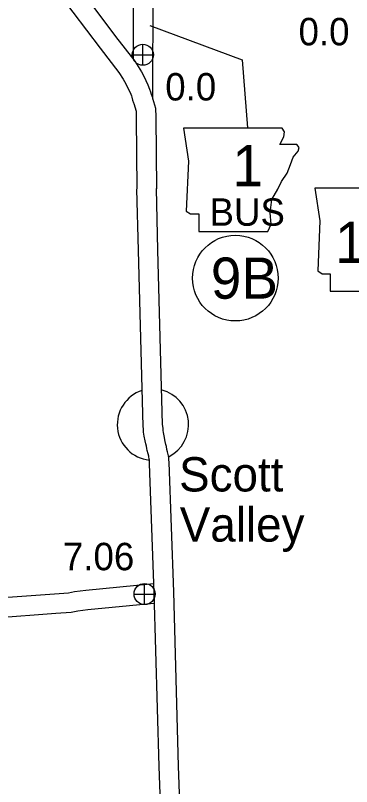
# Model space of a CAD drawing. Extents: x -939622 to -934222, y 1383701 to 1385301.
# Drawn here: x -935782 to -935766.45, y 1384146.23 to 1384181.86 of the extents above; entities that cross this region are included whole.
import ezdxf

# ---------------------------------------------------------------- set-up
doc = ezdxf.new("R2010")
doc.units = 0
for name, color, linetype in [('Level 10', 7, 'Continuous'), ('Level 21', 7, 'Continuous'), ('Level 24', 7, 'Continuous'), ('Level 25', 7, 'Continuous'), ('Level 26', 7, 'Continuous'), ('Level 27', 7, 'Continuous')]:
    doc.layers.add(name, color=color, linetype=linetype)

msp = doc.modelspace()

# ---------------------------------------------------------------- linework, layer by layer
at = {"layer": 'Level 10'}
for points in [[(-935775.638, 1384177.983), (-935775.627, 1384183.177), (-935775.684, 1384187.654), (-935778.687, 1384187.545)], [(-935776.534, 1384179.887), (-935776.527, 1384183.172), (-935776.573, 1384186.721), (-935778.655, 1384186.646)], [(-935779.255, 1384183.412), (-935777.367, 1384180.887), (-935776.471, 1384179.742), (-935776.243, 1384179.374), (-935776.172, 1384179.256), (-935776.045, 1384179.019), (-935775.96, 1384178.849), (-935775.869, 1384178.648), (-935775.787, 1384178.449), (-935775.747, 1384178.322), (-935775.719, 1384178.212), (-935775.676, 1384178.104), (-935775.657, 1384178.037), (-935775.517, 1384177.575)], [(-935779.968, 1384182.862), (-935778.082, 1384180.341), (-935777.21, 1384179.226), (-935777.011, 1384178.905), (-935776.955, 1384178.811), (-935776.845, 1384178.606), (-935776.774, 1384178.463), (-935776.695, 1384178.29), (-935776.633, 1384178.139), (-935776.613, 1384178.075), (-935776.577, 1384177.935), (-935776.528, 1384177.812), (-935776.52, 1384177.783), (-935776.414, 1384177.43)], [(-935776.414, 1384177.43), (-935776.406, 1384177.133), (-935776.376, 1384173.839)], [(-935775.517, 1384177.575), (-935775.506, 1384177.15), (-935775.476, 1384173.847)], [(-935774.547, 1384123.471), (-935774.788, 1384131.051), (-935775.054, 1384139.145), (-935775.353, 1384147.15), (-935775.575, 1384155.194), (-935775.787, 1384161.148), (-935775.795, 1384161.271), (-935775.799, 1384161.32), (-935775.803, 1384161.348), (-935775.812, 1384161.383), (-935775.824, 1384161.445), (-935775.833, 1384161.488), (-935775.863, 1384161.604), (-935775.895, 1384161.756), (-935775.914, 1384161.844), (-935775.937, 1384161.952), (-935775.97, 1384162.067), (-935775.99, 1384162.198), (-935776.035, 1384162.426), (-935776.068, 1384162.604), (-935776.065, 1384162.737), (-935776.085, 1384162.878), (-935776.304, 1384170.996), (-935776.376, 1384173.832)], [(-935773.648, 1384123.5), (-935773.888, 1384131.08), (-935774.155, 1384139.177), (-935774.453, 1384147.179), (-935774.676, 1384155.222), (-935774.888, 1384161.195), (-935774.898, 1384161.342), (-935774.905, 1384161.425), (-935774.918, 1384161.516), (-935774.933, 1384161.576), (-935774.943, 1384161.629), (-935774.957, 1384161.692), (-935774.986, 1384161.808), (-935775.015, 1384161.943), (-935775.034, 1384162.034), (-935775.064, 1384162.17), (-935775.089, 1384162.257), (-935775.103, 1384162.353), (-935775.151, 1384162.596), (-935775.166, 1384162.675), (-935775.163, 1384162.789), (-935775.186, 1384162.954), (-935775.404, 1384171.019), (-935775.476, 1384173.855)], [(-935783.01, 1384154.93), (-935780.19, 1384155.135), (-935779.534, 1384155.18), (-935779.265, 1384155.235), (-935779.001, 1384155.273), (-935778.741, 1384155.307), (-935775.587, 1384155.615)], [(-935782.96, 1384154.031), (-935780.127, 1384154.237), (-935779.413, 1384154.286), (-935779.111, 1384154.348), (-935778.879, 1384154.381), (-935778.639, 1384154.412), (-935775.592, 1384154.71)]]:
    msp.add_lwpolyline(points, dxfattribs=at)
at = {"layer": 'Level 21'}
for p, q in [((-935775.78, 1384181.387), (-935771.514, 1384179.808)), ((-935771.514, 1384179.808), (-935771.265, 1384176.659)), ((-935769.658, 1384176.651), (-935769.658, 1384176.651)), ((-935769.658, 1384176.651), (-935769.658, 1384176.651))]:
    msp.add_line(p, q, dxfattribs=at)
for points in [[(-935774.226, 1384176.651), (-935773.998, 1384175.129), (-935774.099, 1384172.82), (-935773.896, 1384172.693), (-935773.516, 1384172.693), (-935773.516, 1384171.881), (-935770.318, 1384171.881), (-935770.166, 1384172.211), (-935770.217, 1384172.743), (-935770.141, 1384173.353), (-935769.861, 1384173.835), (-935769.684, 1384174.19), (-935769.43, 1384174.571), (-935769.278, 1384174.977), (-935769.151, 1384175.307), (-935768.923, 1384175.586), (-935768.872, 1384175.763), (-935768.973, 1384175.89), (-935769.76, 1384175.89), (-935769.582, 1384176.245), (-935769.557, 1384176.474), (-935769.662, 1384176.649)], [(-935768.142, 1384173.882), (-935767.914, 1384172.36), (-935768.015, 1384170.05), (-935767.812, 1384169.923), (-935767.431, 1384169.923), (-935767.431, 1384169.111), (-935764.234, 1384169.111), (-935764.082, 1384169.441), (-935764.132, 1384169.974), (-935764.056, 1384170.583), (-935763.777, 1384171.065), (-935763.599, 1384171.421), (-935763.346, 1384171.801), (-935763.193, 1384172.207), (-935763.067, 1384172.537), (-935762.838, 1384172.816), (-935762.787, 1384172.994), (-935762.889, 1384173.121), (-935763.676, 1384173.121), (-935763.498, 1384173.476), (-935763.473, 1384173.705), (-935763.578, 1384173.88)]]:
    msp.add_lwpolyline(points, close=True, dxfattribs=at)
at = {"layer": 'Level 24'}
for start, end in [(107.8503, 264.0626), (296.9729, 75.2803)]:
    msp.add_arc((-935775.635, 1384162.955), 1.65, start, end, dxfattribs=at)
at = {"layer": 'Level 26'}
for p, q in [((-935776.103, 1384179.552), (-935776.103, 1384180.527)), ((-935776.59, 1384180.039), (-935775.615, 1384180.039)), ((-935776.022, 1384154.639), (-935776.022, 1384155.614)), ((-935776.509, 1384155.126), (-935775.534, 1384155.126))]:
    msp.add_line(p, q, dxfattribs=at)
for centre in [(-935776.103, 1384180.039), (-935776.022, 1384155.126)]:
    msp.add_circle(centre, 0.487, dxfattribs=at)
at = {"layer": 'Level 27'}
msp.add_circle((-935771.825, 1384169.722), 1.98, dxfattribs=at)

# ---------------------------------------------------------------- texts
at = {"layer": 'Level 21'}
for s, height, p in [('1', 1.901, (-935771.956, 1384173.964)), ('BUS', 1.2672, (-935773.017, 1384172.139)), ('185', 1.9008, (-935767.211, 1384170.423))]:
    msp.add_text(s, height=height, dxfattribs=at).set_placement(p)
at = {"layer": 'Level 24'}
for s, p in [('Scott', (-935774.427, 1384159.864)), ('Valley', (-935774.396, 1384157.547))]:
    msp.add_text(s, height=1.584, dxfattribs=at).set_placement(p)
at = {"layer": 'Level 25'}
for s, p in [('0.0', (-935768.9, 1384180.476)), ('0.0', (-935775.065, 1384177.928)), ('7.06', (-935779.798, 1384156.224))]:
    msp.add_text(s, height=1.2672, dxfattribs=at).set_placement(p)
at = {"layer": 'Level 27'}
msp.add_text('9B', height=1.9008, dxfattribs=at).set_placement((-935772.959, 1384168.771))

doc.saveas('drawing.dxf')
